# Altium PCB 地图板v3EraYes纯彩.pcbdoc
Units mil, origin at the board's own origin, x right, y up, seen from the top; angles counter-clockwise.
Board outline 5260 x 2628.07 mil, 2 copper layers (Top Layer, Bottom Layer); 76 components, 11 nets, 236 pads, 2 vias.
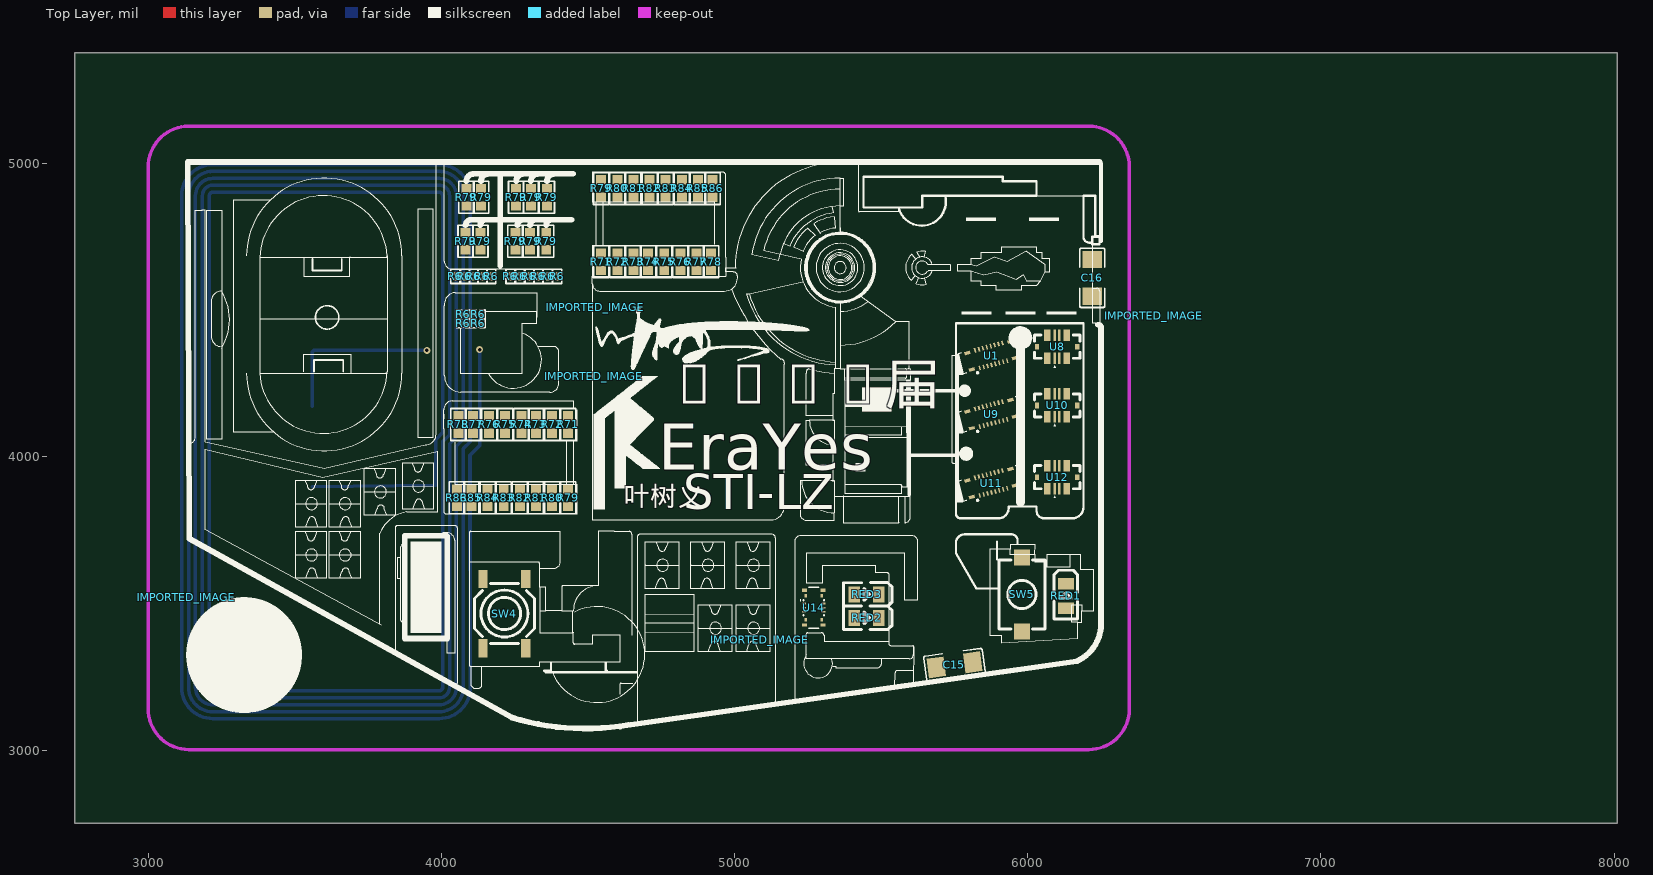
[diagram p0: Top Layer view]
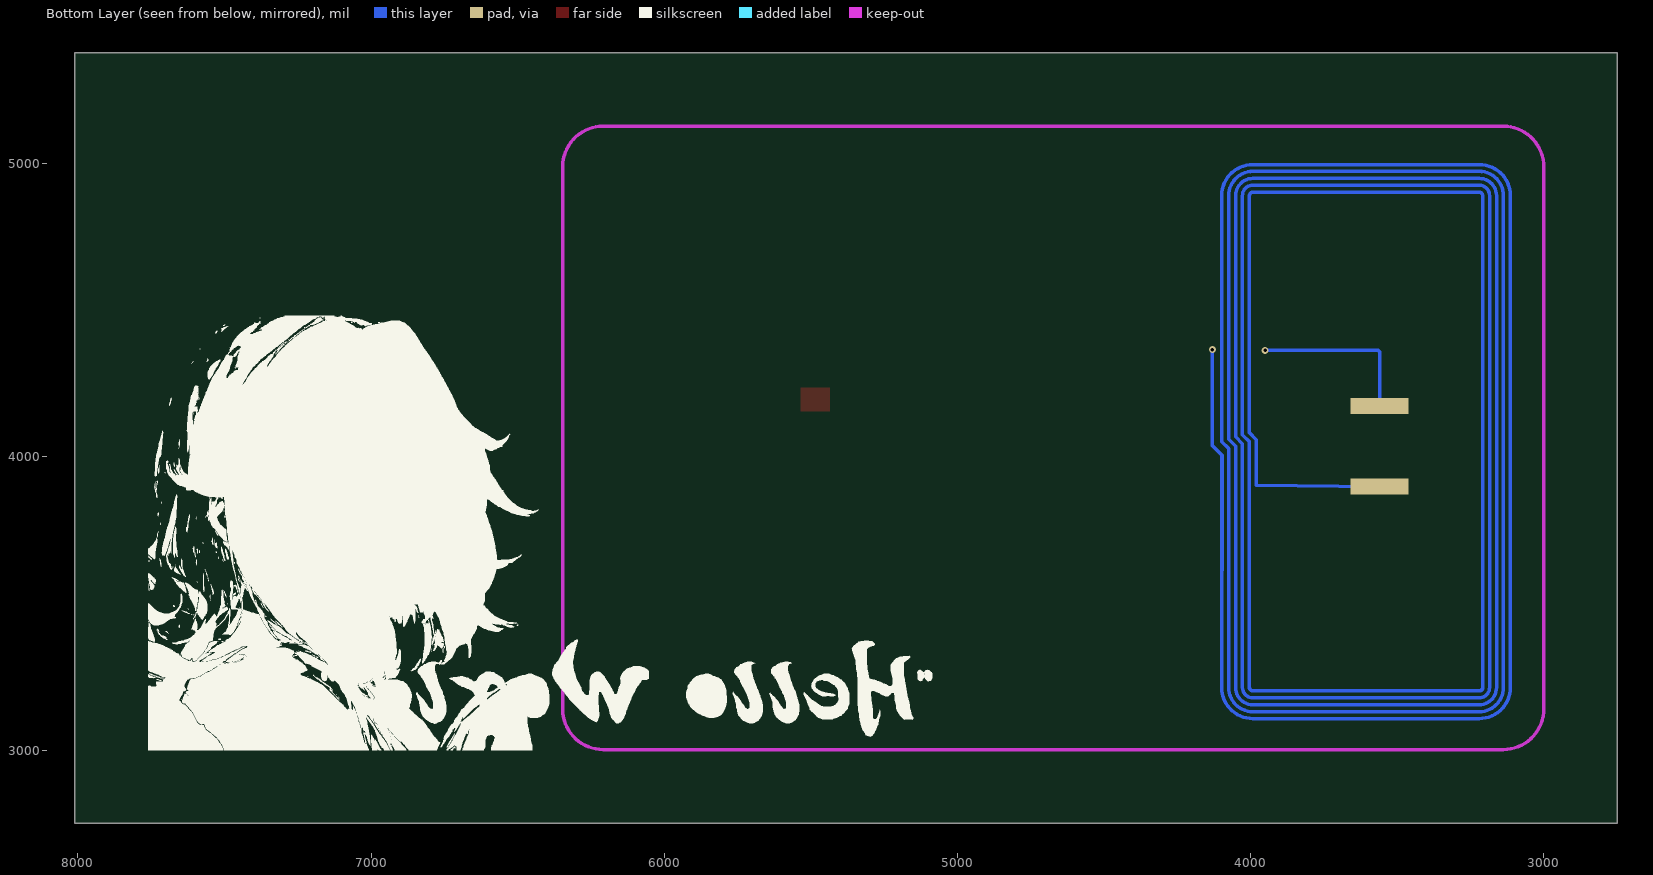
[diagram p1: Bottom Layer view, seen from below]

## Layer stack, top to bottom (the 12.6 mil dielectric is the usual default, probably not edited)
Top Layer: signal copper (thickness not stored)
Dielectric: dielectric 12.6, FR-4, Dk 4.8
Bottom Layer: signal copper (thickness not stored)

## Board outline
8010,2750 2750,2750 2750,5378.07 8010,5378.07

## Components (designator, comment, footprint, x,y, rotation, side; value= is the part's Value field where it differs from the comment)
C15 "0.1u" C1206 5750,3291.07 r8 top
C16 "0.1u" C1206 6220,4611.07 r90 top
IMPORTED_IMAGE "IMPORTED_IMAGE" IMPORTED_IMAGE 3130,3521.07 r0 top
IMPORTED_IMAGE "IMPORTED_IMAGE" IMPORTED_IMAGE 4520,4276.07 r0 top
IMPORTED_IMAGE "IMPORTED_IMAGE" IMPORTED_IMAGE 5085,3376.07 r0 top
IMPORTED_IMAGE "IMPORTED_IMAGE" IMPORTED_IMAGE 6430,4481.07 r0 top
IMPORTED_IMAGE "IMPORTED_IMAGE" IMPORTED_IMAGE 4525,4511.07 r0 top
R6 "1k" R0201 4125,4456.07 r0 top
R6 "1k" R0201 4125,4486.07 r0 top
R6 "1k" R0201 4075,4456.07 r0 top
R6 "1k" R0201 4075,4486.07 r0 top
R6 "1k" R0201 4046.87,4616.07 r270 top
R6 "1k" R0201 4080,4616.07 r270 top
R6 "1k" R0201 4110,4616.07 r270 top
R6 "1k" R0201 4140,4616.07 r270 top
R6 "1k" R0201 4170,4616.07 r270 top
R6 "1k" R0201 4235.53,4616.07 r270 top
R6 "1k" R0201 4267.97,4616.07 r270 top
R6 "1k" R0201 4300,4616.07 r270 top
R6 "1k" R0201 4329.96,4616.07 r270 top
R6 "1k" R0201 4362.39,4616.07 r270 top
R6 "1k" R0201 4395,4616.07 r270 top
R71 "1k" R0603 4545,4666.07 r90 top
R71 "1k" R0603 4432.5,4111.07 r270 top
R72 "1k" R0603 4600,4666.07 r90 top
R72 "1k" R0603 4377.5,4111.07 r270 top
R73 "1k" R0603 4655,4666.07 r90 top
R73 "1k" R0603 4322.5,4111.07 r270 top
R74 "1k" R0603 4705,4666.07 r90 top
R74 "1k" R0603 4272.5,4111.07 r270 top
R75 "1k" R0603 4760,4666.07 r90 top
R75 "1k" R0603 4217.5,4111.07 r270 top
R76 "1k" R0603 4815,4666.07 r90 top
R76 "1k" R0603 4162.5,4111.07 r270 top
R77 "1k" R0603 4870,4666.07 r90 top
R77 "1k" R0603 4107.5,4111.07 r270 top
R78 "1k" R0603 4920,4666.07 r90 top
R78 "1k" R0603 4057.5,4111.07 r270 top
R79 "1k" R0603 4545,4916.07 r90 top
R79 "1k" R0603 4432.5,3861.07 r270 top
R79 "1k" R0603 4085,4886.07 r90 top
R79 "1k" R0603 4135,4886.07 r90 top
R79 "1k" R0603 4255,4886.07 r90 top
R79 "1k" R0603 4305,4886.07 r90 top
R79 "1k" R0603 4360,4886.07 r90 top
R79 "1k" R0603 4082.5,4736.07 r90 top
R79 "1k" R0603 4132.5,4736.07 r90 top
R79 "1k" R0603 4252.5,4736.07 r90 top
R79 "1k" R0603 4357.5,4736.07 r90 top
R79 "1k" R0603 4302.5,4736.07 r90 top
R80 "1k" R0603 4600,4916.07 r90 top
R80 "1k" R0603 4377.5,3861.07 r270 top
R81 "1k" R0603 4655,4916.07 r90 top
R81 "1k" R0603 4322.5,3861.07 r270 top
R82 "1k" R0603 4710,4916.07 r90 top
R82 "1k" R0603 4267.5,3861.07 r270 top
R83 "1k" R0603 4765,4916.07 r90 top
R83 "1k" R0603 4212.5,3861.07 r270 top
R84 "1k" R0603 4820,4916.07 r90 top
R84 "1k" R0603 4157.5,3861.07 r270 top
R85 "1k" R0603 4875,4916.07 r90 top
R85 "1k" R0603 4102.5,3861.07 r270 top
R86 "1k" R0603 4925,4916.07 r90 top
R86 "1k" R0603 4052.5,3861.07 r270 top
RED1 "LED0805-R-RD" LED0805-R-RD 6130,3526.07 r270 top
RED2 "LED0805-R-RD" LED0805-R-RD 5450,3451.07 r180 top
RED3 "LED0805-R-RD" LED0805-R-RD 5450,3531.07 r180 top
SW4 "SW-SMD_4P-L5.2-W5.2-P3.70-LS6.4" SW-SMD_4P-L5.2-W5.2-P3.70-LS6.4 4215,3466.07 r90 top
SW5 "YTS1C0192ABG00" SW-SMD_L6.0-W4.0-LS7.2 5980,3531.07 r90 top
U1 "CONN-SMD_BM28B0.6-16DS-2-0.35V-51" CONN-SMD_BM28B0.6-16DS-2-0.35V-51 5875,4346.07 r15 top
U8 "CONN-SMD_BM25-4P-2-V-51" CONN-SMD_BM25-4P-2-V-51 6100,4376.07 r0 top
U9 "CONN-SMD_BM28B0.6-16DS-2-0.35V-51" CONN-SMD_BM28B0.6-16DS-2-0.35V-51 5875,4146.07 r15 top
U10 "CONN-SMD_BM25-4P-2-V-51" CONN-SMD_BM25-4P-2-V-51 6100,4176.07 r0 top
U11 "CONN-SMD_BM28B0.6-16DS-2-0.35V-51" CONN-SMD_BM28B0.6-16DS-2-0.35V-51 5875,3911.07 r15 top
U12 "CONN-SMD_BM25-4P-2-V-51" CONN-SMD_BM25-4P-2-V-51 6100,3931.07 r0 top
U14 "CONN-SMD_AXG106144" CONN-SMD_AXG106144 5270,3486.07 r270 top

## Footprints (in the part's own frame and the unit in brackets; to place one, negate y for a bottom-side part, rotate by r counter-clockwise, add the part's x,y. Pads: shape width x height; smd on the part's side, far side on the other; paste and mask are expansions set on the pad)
C1206 [mm]
  rect 1.485x1.728 smd paste-100 mask+0.051: 1(-1.593,0) 2(1.593,0)
  silkscreen extent -2.56,-1.09 2.56,1.09
CONN-SMD_AXG106144 [mm]
  rect 0.15x0.35 smd paste+0 mask+0.05: 1(-0.35,-0.845) 2(-0.35,0.845) 3(0,-0.845) 4(0,0.845) 5(0.35,-0.845) 6(0.35,0.845)
  rect 0.3x0.22 smd paste+0 mask+0.05: 7(1.03,0.69) 8(1.03,-0.69) 11(-1.03,-0.69) 12(-1.03,0.69)
  rect 0.28x0.4 smd paste+0 mask+0.05: 9(1.5,0.8) 10(1.5,-0.8) 13(-1.5,-0.8) 14(-1.5,0.8)
  silkscreen extent -1.78,-1.17 1.78,0.89
CONN-SMD_BM25-4P-2-V-51 [mm]
  rect 0.2x1 smd: 1(-0.2,-1) 2(-0.2,1) 3(0.2,-1) 4(0.2,1)
  rect 0.58x1 smd: 5(0.85,-1) 6(0.85,1) 7(-0.85,1) 8(-0.85,-1)
  rect 0.38x0.5 smd: 9(-1.735,0) 10(1.735,0)
  silkscreen extent -1.97,-1.8 1.97,1
CONN-SMD_BM28B0.6-16DS-2-0.35V-51 [mm]
  rect 0.15x0.41 smd: 1(-1.225,-0.795) 2(-0.875,-0.795) 3(-0.525,-0.795) 4(-0.175,-0.795) 5(0.175,-0.795) 6(0.525,-0.795) 7(0.875,-0.795) 8(1.225,-0.795) 9(1.225,0.795) 10(0.875,0.795) 11(0.525,0.795) 12(0.175,0.795) 13(-0.175,0.795) 14(-0.525,0.795) 15(-0.875,0.795) 16(-1.225,0.795)
  rect 0.53x0.31 smd: 17(-1.93,0.745) 18(-1.93,-0.745) 19(1.93,-0.745) 20(1.93,0.745)
  silkscreen extent -2.73,-1.22 2.67,0.9
IMPORTED_IMAGE [mil]
  silkscreen extent 0,-394 394,0
LED0805-R-RD [mm]
  rect 1x1.4 smd: 1(1.05,0) 2(-1.05,0)
  silkscreen extent -2.22,-1.04 1.99,1.01
R0201 [mil]
  rect 11.93x12.76 smd paste-3937.01 mask+2: 1(-9.51,0) 2(9.51,0)
  silkscreen extent -24,-15 24,15
R0603 [mil]
  rect 31.75x34.02 smd paste-3937.01 mask+2: 1(-29.66,0) 2(29.66,0)
  silkscreen extent -55,-26 55,26
SW-SMD_4P-L5.2-W5.2-P3.70-LS6.4 [mm]
  rect 1.58x0.8 smd: 1(-3,1.85) 2(3,1.85) 3(-3,-1.85) 4(3,-1.85)
  silkscreen extent -2.6,-2.6 2.6,2.6
SW-SMD_L6.0-W4.0-LS7.2 [mm]
  rect 1.4x1.4 smd paste+0 mask+0.05: 1(-3.2,0) 2(3.2,0)
  silkscreen extent -3,-2 3,2

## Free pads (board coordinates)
  rect 196.85x55.12 smd far side paste+0 mask-196.85: 11(3560,3898.78) 11(3560,4173.78)

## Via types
v1: diameter 24, hole 12, Top Layer to Bottom Layer, 2 vias

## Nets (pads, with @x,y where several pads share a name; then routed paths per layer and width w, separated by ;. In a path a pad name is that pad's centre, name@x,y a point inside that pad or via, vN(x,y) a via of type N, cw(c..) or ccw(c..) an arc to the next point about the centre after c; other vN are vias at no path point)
C5_1: C15.1 C16.1
C5_2: C15.2 C16.2
R3_1: R71.1 R72.1 R73.1 R74.1 R75.1 R76.1 R77.1 R78.1 R79.1 R80.1 R81.1 R82.1 R83.1 R84.1 R85.1 R86.1
R3_2: R71.2 R72.2 R73.2 R74.2 R75.2 R76.2 R77.2 R78.2 R79.2 R80.2 R81.2 R82.2 R83.2 R84.2 R85.2 R86.2
R6_1: R6.1
R6_2: R6.2
S$48780: pad.11@3560,3898.78 | length 1417.4
  Bottom Layer w12: pad.11@3560,3898.78 3980,3903.78 3980,4058.78 4003.8,4082.58 4003.8,4891.28
S$48796: pad.11@3560,4173.78 | length 950.6
  Bottom Layer w12.01: pad.11@3560,4173.78 3560,4358.78 3565,4363.78 v1(3950,4363.78) ; 4097.45,4006.01 4130,4038.56 v1(4130,4366.07)
SW1_1: SW5.1
SW1_2: SW5.2
"": RED1.1 RED1.2 RED2.1 RED2.2 RED3.1 RED3.2 SW4.1 SW4.2 SW4.3 SW4.4 U1.1 U1.2 U1.3 U1.4 U1.5 U1.6 U1.7 U1.8 U1.9 U1.10 U1.11 U1.12 U1.13 U1.14 U1.15 U1.16 U1.17 U1.18 U1.19 U1.20 U8.1 U8.2 U8.3 U8.4 U8.5 U8.6 U8.7 U8.8 U8.9 U8.10 U9.1 U9.2 U9.3 U9.4 U9.5 U9.6 U9.7 U9.8 U9.9 U9.10 U9.11 U9.12 U9.13 U9.14 U9.15 U9.16 U9.17 U9.18 U9.19 U9.20 U10.1 U10.2 U10.3 U10.4 U10.5 U10.6 U10.7 U10.8 U10.9 U10.10 U11.1 U11.2 U11.3 U11.4 U11.5 U11.6 U11.7 U11.8 U11.9 U11.10 U11.11 U11.12 U11.13 U11.14 U11.15 U11.16 U11.17 U11.18 U11.19 U11.20 U12.1 U12.2 U12.3 U12.4 U12.5 U12.6 U12.7 U12.8 U12.9 U12.10 U14.1 U14.2 U14.3 U14.4 U14.5 U14.6 U14.7 U14.8 U14.9 U14.10 U14.11 U14.12 U14.13 U14.14 | length 25507.2
  Bottom Layer w12: 3220,3154.72 cw(c3220,3213.78) 3160.95,3213.78 3160.95,4891.36 cw(c3219.97,4891.33) 3220,4950.36 3991.83,4950.36 cw(c3991.83,4891.36) 4050.83,4891.36 4050.83,4068.36 4027.83,4044.49 4027.83,3213.78 cw(c3992.11,3214.06) 3991.83,3178.35 3220,3178.35 cw(c3220,3213.78) 3184.57,3213.78 3184.57,4891.36 cw(c3220.28,4891.64) 3220,4927.36 3991.83,4927.36 cw(c3991.83,4891.36) 4027.83,4891.36 4027.83,4076.36 4003.83,4052.36 4003.83,3213.78 cw(c3991.92,3213.87) 3991.83,3201.97 3220,3201.97 cw(c3220,3213.78) 3208.19,3213.78 3208.19,4891.36 cw(c3220.09,4891.46) 3220,4903.36 3991.83,4903.36 cw(c3991.83,4891.36) 4003.83,4891.36 ; 3220,3154.73 3991.83,3154.73 ; 3991.83,3154.72 ccw(c3991.8,3213.75) 4050.83,3213.78 4050.83,4036.62 4074.83,4060.36 4074.83,4891.36 ccw(c3991.83,4891.36) 3991.83,4974.36 3220,4974.36 ccw(c3220.16,4891.52) 3137.32,4891.36 3137.32,3213.78 ccw(c3220,3213.78) 3220,3131.1 3991.83,3131.1 ccw(c3991.99,3213.94) 4074.83,3213.78 4074.83,4028.74 4098.83,4052.36 4098.83,4891.36 ccw(c3992.33,4890.86) 3991.83,4997.36 3220,4997.36 ccw(c3219.85,4891.21) 3113.7,4891.36 3113.7,3213.78 ccw(c3220,3213.78) 3220,3107.48 3991.83,3107.48 ccw(c3992.18,3214.13) 4098.83,3213.78 4097.44,4006.04

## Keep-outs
Board Outline Layer:
  lines w11.81 net "": 3000,3139.88 ccw(c3137.8,3139.88) 3137.8,3002.09 6208.66,3002.09 ccw(c6208.65,3139.88) 6346.45,3139.88 6346.45,4990.27 ccw(c6208.65,4990.27) 6208.65,5128.07 3137.8,5128.07 ccw(c3137.8,4990.27) 3000,4990.27 3000,3139.88

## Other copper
Top Layer:
  region net "": 5535,4156.07 5535,4236.07 5435,4236.07 5435,4156.07

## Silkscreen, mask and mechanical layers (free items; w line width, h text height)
Top Silkscreen Layer:
  drawing of 749 lines, arcs and shapes, not listed
  text "2025届" at 4770.83,4181.15 h135.94
  text "EraYes" at 4740,3956.07 h157.48
  text "叶树义" at 4620.08,3833.41 h66.9
  text "STI-LZ" at 4825,3821.07 h120
Bottom Solder Mask Layer:
  region net "": 3465,4143.78 3655,4143.78 3655,4198.78 3465,4198.78
  region net "": 3465,3873.78 3655,3873.78 3655,3928.78 3465,3928.78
